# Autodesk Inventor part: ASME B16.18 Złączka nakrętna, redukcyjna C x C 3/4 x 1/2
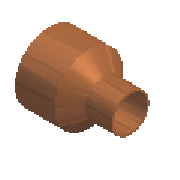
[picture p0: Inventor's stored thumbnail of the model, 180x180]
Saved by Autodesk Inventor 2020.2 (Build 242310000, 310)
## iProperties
NAME: PIPING: ASME B16.18 Reducing Coupling C x C
DATA: <meta><inlinegroups number="1" deflen="6.985"></inlinegroups><connections number="2"></connections><angles><a>3.14159265358979</a></angles></meta>
Manager: www.cadconsulting.pl
Company: Fabian Stasiak CAD Consulting
IsCustomPart: 0
Created: 2014-02
Part Number: ASME B16.18 Złączka nakrętna, redukcyjna C x C 3/4 x 1/2
Material: Miedź, odlew
Description: Złączka nakrętna redukcyjna C x C odlewana ze stopu miedzi, lutowana na wcisk
Document SubType Name: Modeling
Standard: ASME B16.18
Designer: F.Stasiak
Standard Revision: 2001
Standards Organization: ANSI
Language: pl-PL
Size Designation: 3/4 x 1/2
Categories: <MemberInstance><Categories><Category DisplayName="Rury cienko- i grubościenne" InternalName="4347fa0f-2144-441d-94cd-e3e15c92b736" Mnemonic="TUBEANDPIPE"><Cate
Density: 1 g/cm^3
Appearance: Miedź - satynowa
Catalog Web Link: www.expertbooks.pl
Author: F.Stasiak
Subject: Zbiór ćwiczeń. Autodesk Inventor 2020. Kurs Professional
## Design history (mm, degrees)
sketch "Sketch1"
  geometry: L1 (0, 0)-(-39.624, 0); L2 (0, 0)-(0, 11.138); L3 (0, 11.138)-(0, 12.662); L4 (0, 12.662)-(-19.05, 12.662); L5 (-19.05, 12.662)-(-26.924, 9.233); L6 (-26.924, 9.233)-(-39.624, 9.233); L7 (-39.624, 9.233)-(-39.624, 7.963); L8 (-39.624, 7.963)-(-26.924, 7.963); L9 (0, 11.138)-(-19.05, 11.138); L10 (-19.05, 11.138)-(-19.05, 10.122); L11 (-26.924, 7.963)-(-26.924, 6.947); L12 (-19.05, 11.138)-(-19.05, 12.662); L13 (-26.924, 7.963)-(-26.924, 9.233); L14 (-39.624, 0)-(-39.624, 7.963); L15 (-22.987, 10.947)-(-22.987, 9.423); L16 (-22.987, 9.423)-(-22.987, 0); A1 r 11.278 centre (-19.08, -1.156) between (-19.05, 10.122) and (-26.924, 6.947); 1 further point
  constraints: 32 end point, 8 parallel, 5 perpendicular, 3 point on circle, 1 centre point, 1 coincident, 1 collinear, 1 horizontal, 1 midpoint, 1 point on line
  dimensions: "d0" = 7.874 horizontal distance of L11.end L10.end (= N1); "d1" = 1.524 distance of L2.end L3.end (= R1); "d2" = 1.27 distance of L6.end L7.end (= R2); "d3" = 19.05 horizontal distance of L10.end L1.start (= G1); "d4" = 12.7 horizontal distance of L1.end L11.end (= G2); "d5" = 11.1379 distance of L1.start L2.end (= 0.5 x F1); "d6" = 7.9629 distance of L1.end L7.end (= 0.5 x F2); "d7" = 2.54 distance of L10.end L4.end (= T1); "d8" = 2.286 distance of L11.end L5.end (= T2); "d9" = 1.524 distance of L15.start L15.end (= R1)
revolve "Revolution1" sketch "Sketch1" stored, may be unused: angle "d10" = 90 deg
workaxis "Work Axis1"
workpoint "Work Point1"
workpoint "Work Point2"
workaxis "Work Axis2"
workpoint "Work Point3"
workaxis "Work Axis3"
workpoint "Work Point4"
body "Solid1"
other parameters: "N1" = 7.874 [user parameter; used in 1 equation term], "R1" = 1.524 [user parameter; used in 2 equation terms], "T1" = 2.54 [user parameter; used in 1 equation term], "F1" = 22.2758 [user parameter; used in 1 equation term], "G1" = 19.05 [user parameter; used in 1 equation term], "F2" = 15.9258 [user parameter; used in 1 equation term], "G2" = 12.7 [user parameter; used in 1 equation term], "R2" = 1.27 [user parameter; used in 1 equation term], "T2" = 2.286 [user parameter; used in 1 equation term], "Size_Designation" = 12.345 [user parameter]
